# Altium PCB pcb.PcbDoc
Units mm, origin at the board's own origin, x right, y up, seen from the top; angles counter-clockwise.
Board outline 66.48 x 77.37 mm, 2 copper layers (Top Layer, Bottom Layer); 43 components, 40 nets, 214 pads, 135 vias.
Unrouted connection lines stored in the file: 93.
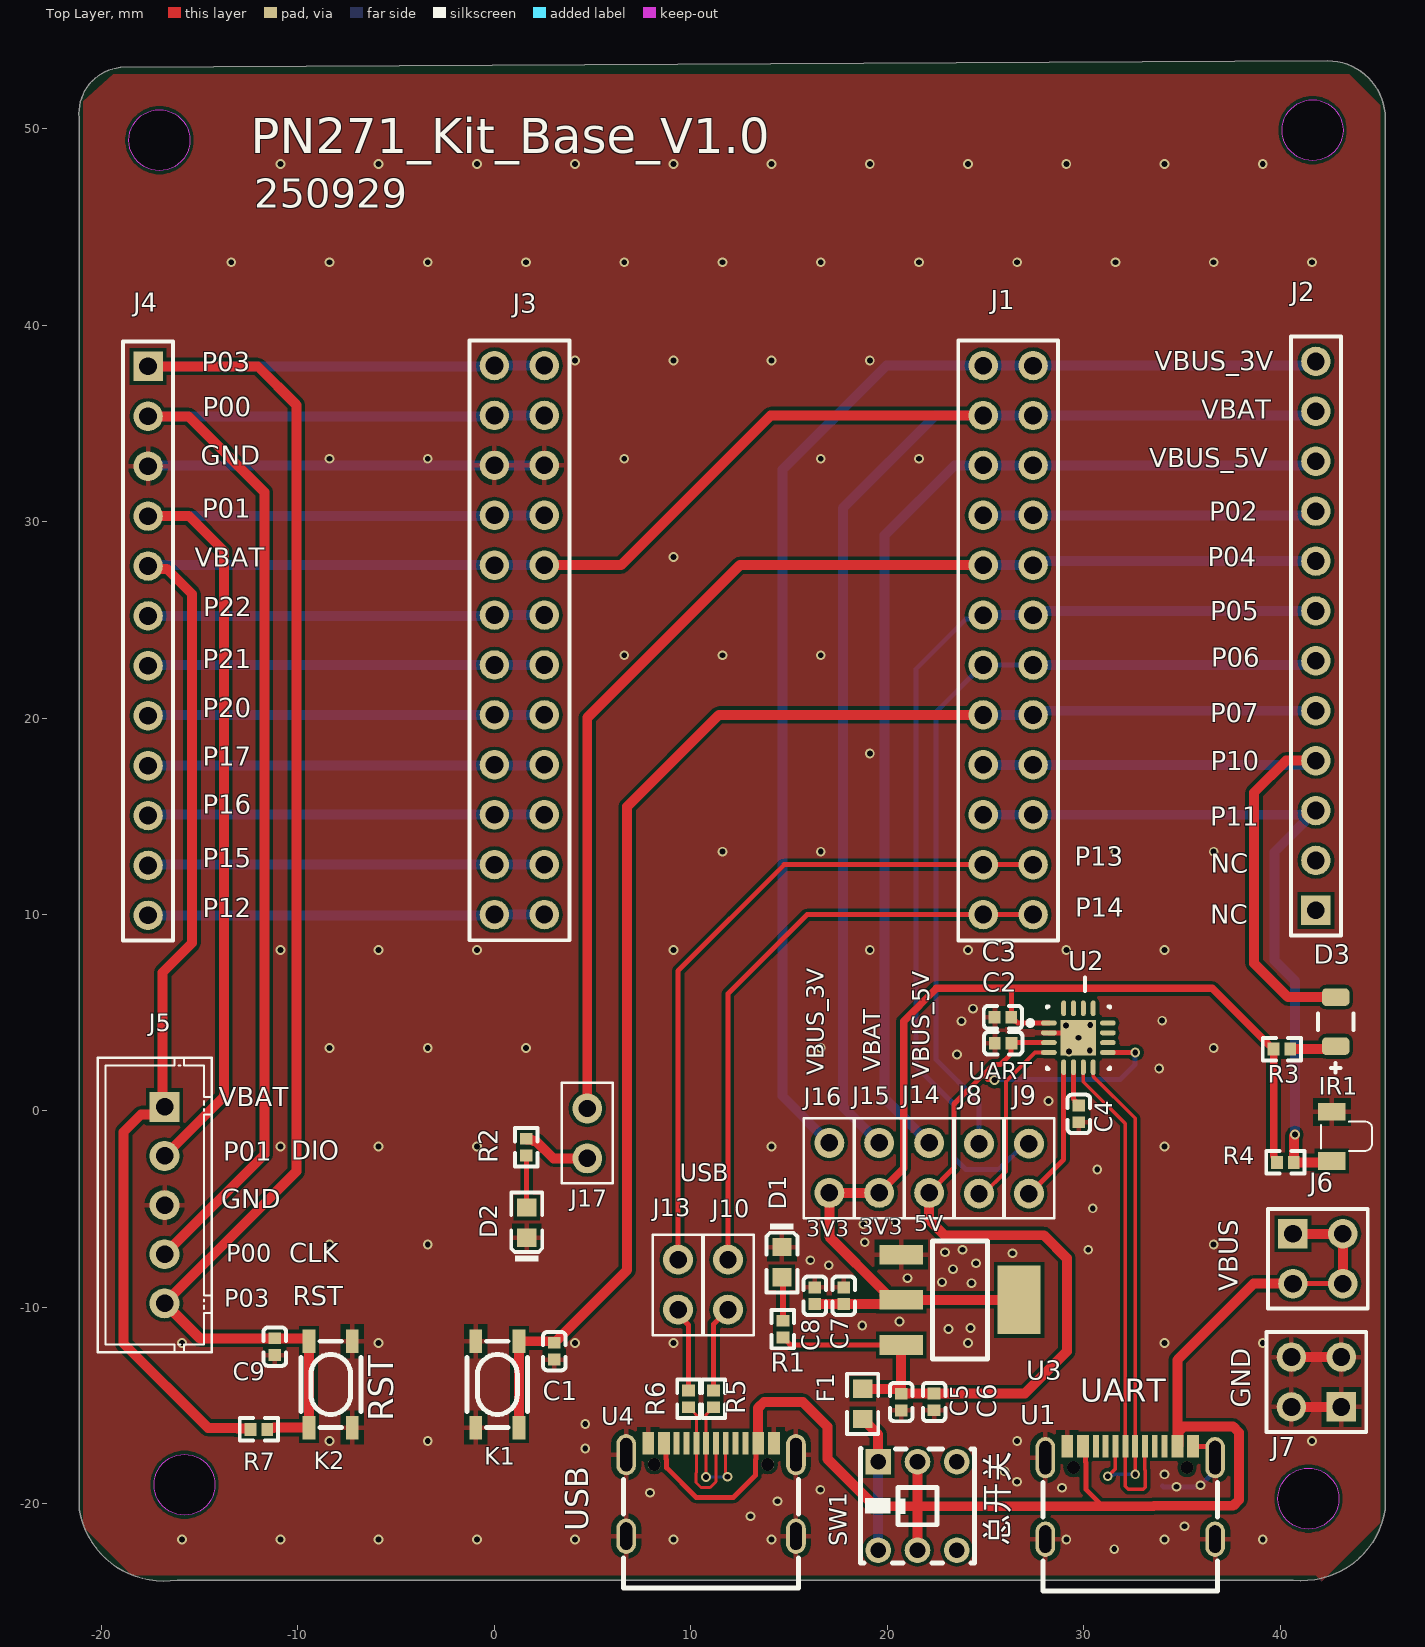
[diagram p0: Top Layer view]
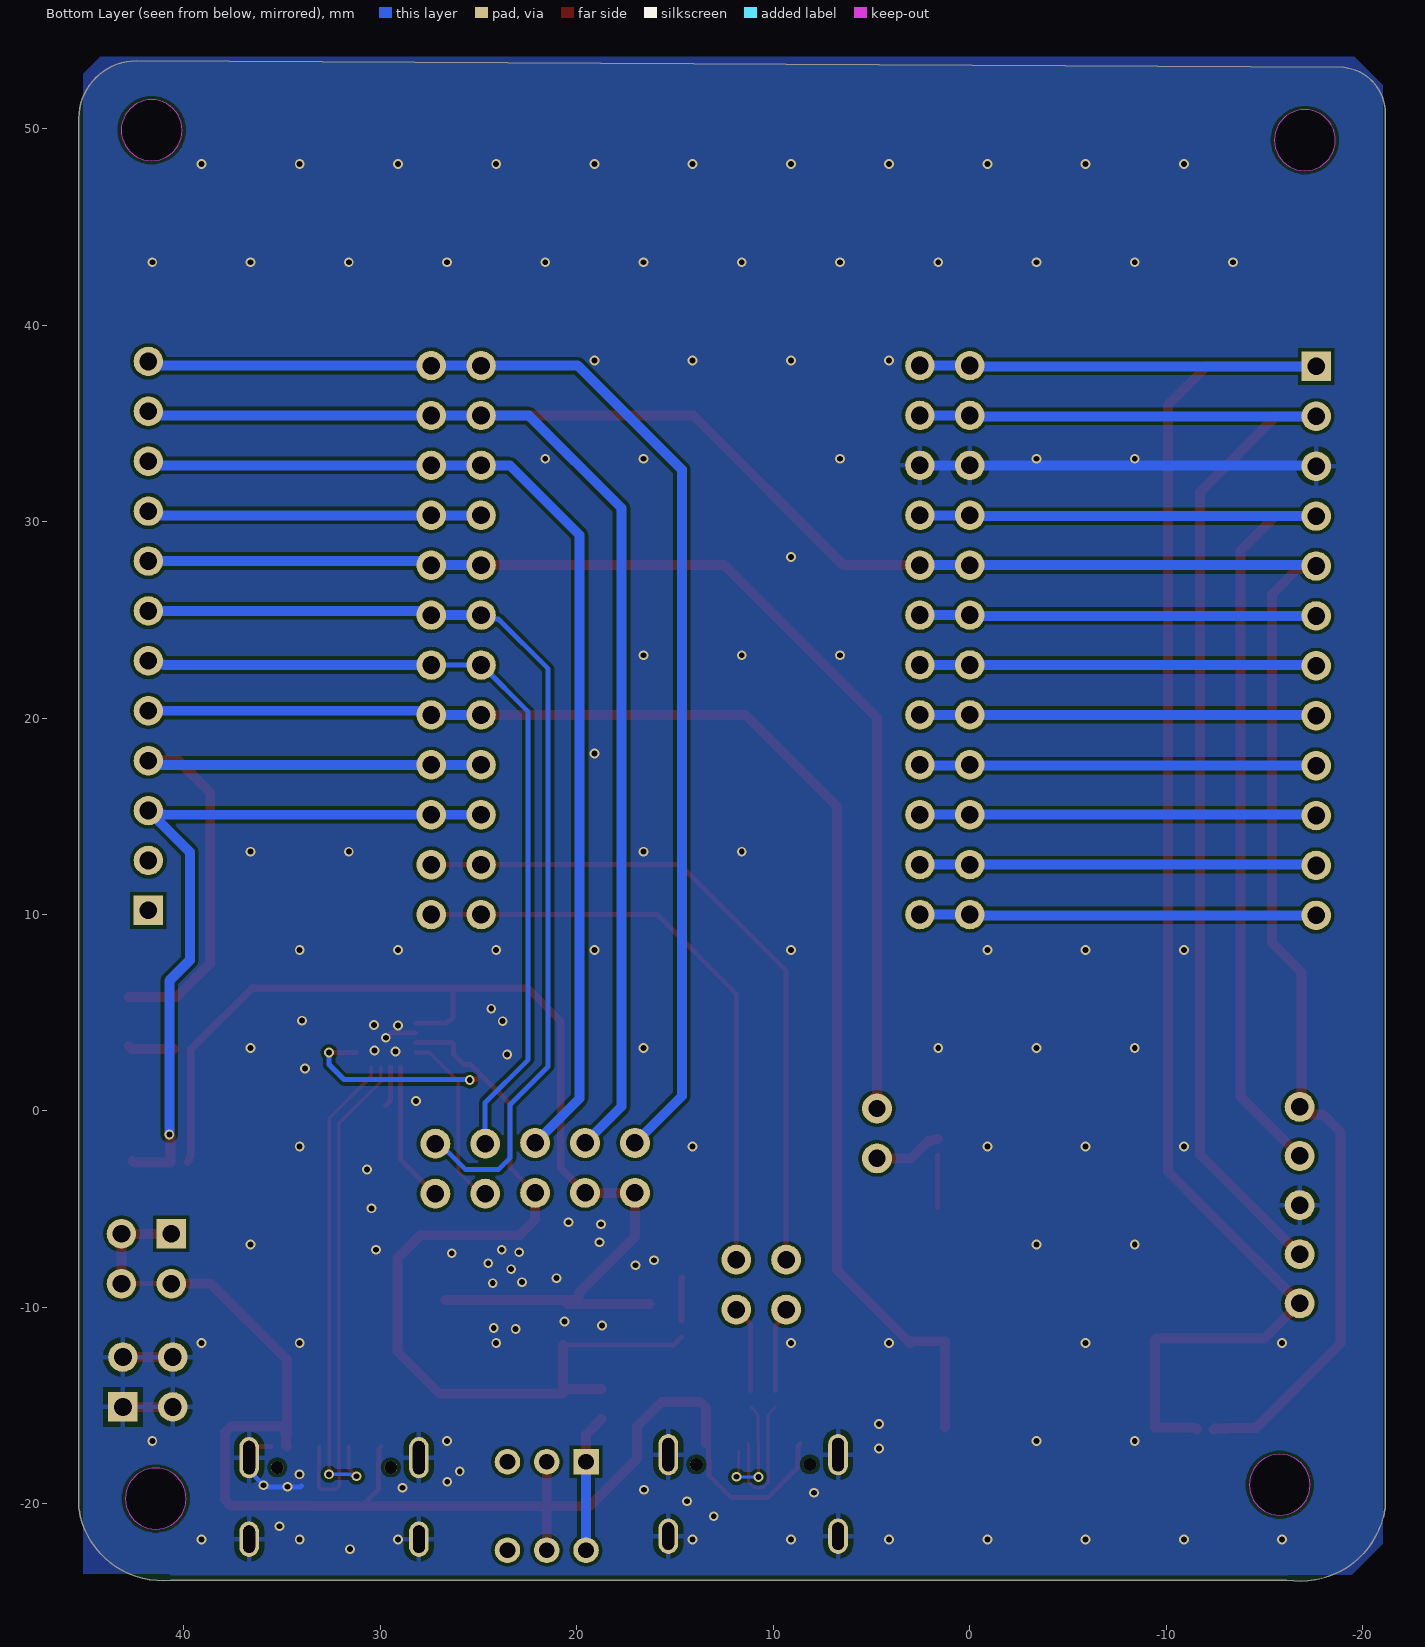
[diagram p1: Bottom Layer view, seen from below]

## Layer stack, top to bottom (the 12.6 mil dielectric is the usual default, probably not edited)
Top Solder: solder mask 0.0102, Solder Resist, Dk 3.5
Top Layer: signal copper 0.0356
Dielectric 1: dielectric 0.32, FR-4, Dk 4.8
Bottom Layer: signal copper 0.0356
Bottom Solder: solder mask 0.0102, Solder Resist, Dk 3.5

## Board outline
-21.13,-20.285 cw(c-20.879,-20.244) -21.133,-20.243 -21.133,-19.254 -21.133,50.559 cw(c-18.809,50.787) -19.051,53.11 cw(c-19.025,52.857) -19.026,53.112 42.417,53.442 cw(c42.418,53.188) 42.418,53.442 cw(c42.418,50.521) 45.339,50.521 cw(c45.085,50.521) 45.339,50.519 45.339,-19.122 45.339,-20.244 cw(c45.085,-20.244) 45.336,-20.283 cw(c41.11,-19.621) 40.667,-23.876 -16.134,-23.876 cw(c-16.827,-19.571)
cut-out: -15.774,-20.575 cw(c-15.774,-19.025) -17.324,-19.025 cw(c-15.774,-19.025) -15.774,-17.475 cw(c-15.774,-19.025) -14.224,-19.025 cw(c-15.774,-19.025)
cut-out: -17.053,47.862 cw(c-17.053,49.412) -18.603,49.412 cw(c-17.053,49.412) -17.053,50.962 cw(c-17.053,49.412) -15.503,49.412 cw(c-17.053,49.412)
cut-out: 41.64,48.37 cw(c41.64,49.92) 40.09,49.92 cw(c41.64,49.92) 41.64,51.47 cw(c41.64,49.92) 43.19,49.92 cw(c41.64,49.92)
cut-out: 41.43,-21.279 cw(c41.43,-19.729) 39.88,-19.729 cw(c41.43,-19.729) 41.43,-18.179 cw(c41.43,-19.729) 42.98,-19.729 cw(c41.43,-19.729)

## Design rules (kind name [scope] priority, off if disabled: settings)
Clearance [All] p1: gap=0.173 ignorepadtopadclearanceinfootprint=FALSE
HoleSize [All] p1: absolutevalues=TRUE maxlimit=3.81 minlimit=0.025 maxpercent=80.000 minpercent=20.000
MinimumSolderMaskSliver [All] p1: minsoldermaskwidth=0.025
PolygonConnect [All] p1: thpad.connectstyle=Relief thpad.reliefconductorwidth=0.254 thpad.reliefentries=4 thpad.polygonreliefangle="90 Angle" thpad.airgapwidth=0.254 smdpad.connectstyle=Relief smdpad.reliefconductorwidth=0.254 smdpad.reliefentries=4 smdpad.polygonreliefangle="90 Angle" smdpad.airgapwidth=0.254 via.connectstyle=Direct via.reliefconductorwidth=0.254 via.reliefentries=4 via.polygonreliefangle="90 Angle" via.airgapwidth=0.254
RoutingVias [All] p1: holewidth=0.3 width=0.5 viastyle="Through Hole" minholewidth=0.3 minwidth=0.5 maxholewidth=0.3 maxwidth=0.5
SilkToSilkClearance [All] p1 off: silktosilkclearance=0.254
SilkToSolderMaskClearance [IsPad] p1 off: minsilkscreentomaskgap=0.254 clearancetoexposedcopper=TRUE
SolderMaskExpansion SolderMaskExpansion_1 [IsVia] p1: expansion=0.102 istentingtop=TRUE
SolderMaskExpansion [All] p2: expansion=0.102 istentingtop=FALSE
UnRoutedNet [All] p1: checkbadconnections=TRUE
Width [All] p1: maxlimit=1.27 minlimit=0.152 preferedwidth=0.203 minimp=50.000000 maximp=50.000000 favimp=50.000000
25 further rules are at their usual default settings.

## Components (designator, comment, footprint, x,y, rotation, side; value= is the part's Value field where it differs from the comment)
C1 "100nF / NC" 0402_C 3.048,-12.224 r90 top
C2 "100nF" 0402_C 25.894,3.449 r180 top
C3 "4.7uF" 0402_C 25.88,4.77 r180 top
C4 "100nF" 0402_C 29.743,-0.146 r270 top
C5 "100nF" 0402_C 20.701,-14.815 r90 top
C6 "10uF" 0402_C 22.377,-14.808 r90 top
C7 "100nF" 0402_C 17.78,-9.405 r270 top
C8 "10uF" 0402_C 16.307,-9.405 r270 top
C9 "100nF / NC" 0402_C -11.176,-11.996 r90 top
D1 "红灯 0603" 0603_LED_S1 14.63,-7.696 r270 top
D2 "绿灯 0603" 0603_LED_S1 1.645,-5.686 r90 top
D3 "IR26-51C/L110/TR8" FP-IR26-51C-L110-TR8-MFG 42.816,4.547 r90 top
F1 "" 0603_R 18.745,-14.91 r90 top
IR1 "PT26-51B/TR8" OPTO-SMD_PT26-51B-TR8 42.621,-1.295 r270 top
J1 "Header 2x12" "Header 2X12" 24.875,37.938 r270 top locked
J2 "nc" HDR1X12 41.808,10.211 r90 top
J3 "Header 2x12" "Header 2X12" 0,37.94 r270 top locked
J4 "nc" HDR1X12 -17.628,37.897 r270 top
J5 "SWD" "XH 1x5" -16.789,0.21 r270 top
J6 "Header 2X2" HDR2X2 40.64,-6.248 r270 top
J7 "Header 2X2" HDR2X2 43.104,-15.062 r90 top
J8 "Header 2" "Header 1x2" 24.663,-1.666 r0 top
J9 "Header 2" "Header 1x2" 27.203,-1.666 r0 top
J10 "Header 2" "Header 1x2" 11.887,-10.109 r180 top
J13 "Header 2" "Header 1x2" 9.347,-10.109 r180 top
J14 "Header 2" "Header 1x2" 22.123,-4.166 r180 top
J15 "Header 2" "Header 1x2" 19.583,-4.166 r180 top
J16 "Header 2" "Header 1x2" 17.043,-4.166 r180 top
J17 "Header 2" "Header 1x2" 4.724,0.127 r0 top
K1 "K2-1808GN-A4SW-04" KEY-SMD_4P-L4.2-W3.2-P2.20-LS5.1-TL 0.152,-13.919 r270 top
K2 "K2-1808GN-A4SW-04" KEY-SMD_4P-L4.2-W3.2-P2.20-LS5.1-TL -8.331,-13.919 r90 top
R1 "1KΩ" 0402_R 14.681,-11.1 r90 top
R2 "1KΩ" 0402_R 1.619,-1.843 r270 top
R3 "100Ω" 0402_R 40.081,3.15 r180 top
R4 "300Ω" 0402_R 40.259,-2.616 r180 top
R5 "0Ω" 0402_R 11.151,-14.649 r270 top
R6 "0Ω" 0402_R 9.881,-14.649 r270 top
R7 "NC" 0402_R -11.989,-16.205 r180 top
SW1 "K8-5851E-L1" SW-TH_6P-L5.8-W5.8-P2.00-LS4.5-TL_K8-5851E-L1 21.533,-20.106 r0 top
U1 "USB_Type-C(Seat-16P)" USB-C-SMD_TYPE-C16PIN 32.36,-19.431 r0 top
U2 "CH343P" QFN16 29.723,3.728 r0 top
U3 "AMS1117-3.3" SOT-223 23.701,-9.613 r180 top
U4 "USB_Type-C(Seat-16P)" USB-C-SMD_TYPE-C16PIN 11.026,-19.279 r0 top

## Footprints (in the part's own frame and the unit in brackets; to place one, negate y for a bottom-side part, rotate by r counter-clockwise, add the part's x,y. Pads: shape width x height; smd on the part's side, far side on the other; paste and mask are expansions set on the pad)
0402_C [mm]
  rect 0.6x0.65 smd mask+0.051: 1(-0.425,0) 2(0.425,0)
  silkscreen extent -0.97,-0.58 0.97,0.58, body extent -0.48,-0.3 0.52,0.3, height 0.2
0402_R [mm]
  rect 0.6x0.65 smd mask+0.051: 1(-0.425,0) 2(0.425,0)
  silkscreen extent -0.97,-0.58 0.97,0.58, body extent -0.57,-0.27 0.58,0.28, height 0.41
0603_LED_S1 [mm]
  rect 0.93x0.98 smd: A(0.77,0) K(-0.77,0)
  silkscreen extent -1.97,-0.79 1.54,0.79, body extent -0.8,-0.4 0.8,0.4, height 0.6
0603_R [mm]
  rect 0.93x0.98 smd: 1(-0.77,0) 2(0.77,0)
  silkscreen extent -1.53,-0.79 1.54,0.79, body extent -0.85,-0.4 0.85,0.4, height 0.56
FP-IR26-51C-L110-TR8-MFG [mm]
  rrect50% 0.9x1.4 smd paste+0 mask+0: 1(-1.25,0) 2(1.25,0)
  silkscreen extent -2.6,-0.9 0.43,0.9, body extent -1.8,-1 1.8,1, height 0.25
HDR1X12 [mm] "Connector; Header; 12 Position"
  rect 1.5x1.5 hole 0.9: 1(0,0)
  round 1.5 hole 0.9: 2(2.54,0) 3(5.08,0) 4(7.62,0) 5(10.16,0) 6(12.7,0) 7(15.24,0) 8(17.78,0) 9(20.32,0) 10(22.86,0) 11(25.4,0) 12(27.94,0)
  silkscreen extent -1.27,-1.27 29.21,1.27
HDR2X2 [mm] "Connector; Header; 2x2 Position"
  rect 1.5x1.5 hole 0.9: 1(0,0)
  round 1.5 hole 0.9: 2(0,2.54) 3(2.54,0) 4(2.54,2.54)
  silkscreen extent -1.27,-1.27 3.81,3.81
"Header 1x2" [mil] "Header 1x2,2.54mm"
  round 60 hole 35: 1(0,0) 2(0,-100)
  silkscreen extent -51,-150 51,51, body extent -50,-150 50,50, height 335
"Header 2X12" [mm] "Connector; Header; 12x2 Position"
  round 1.5 hole 0.9: 1(0,0) 2(0,2.54) 3(2.54,0) 4(2.54,2.54) 5(5.08,0) 6(5.08,2.54) 7(7.62,0) 8(7.62,2.54) 9(10.16,0) 10(10.16,2.54) 11(12.7,0) 12(12.7,2.54) 13(15.24,0) 14(15.24,2.54) 15(17.78,0) 16(17.78,2.54) 17(20.32,0) 18(20.32,2.54) 19(22.86,0) 20(22.86,2.54) 21(25.4,0) 22(25.4,2.54) 23(27.94,0) 24(27.94,2.54)
  silkscreen extent -1.27,-1.27 29.25,3.81, body extent -1.27,-1.27 29.21,3.81, height 8.5
KEY-SMD_4P-L4.2-W3.2-P2.20-LS5.1-TL [mm]
  rect 1.2x0.65 smd: 1(-2.2,1.1) 2(2.2,1.1) 3(-2.2,-1.1) 4(2.2,-1.1)
  silkscreen extent -2.2,-1.55 2.2,1.52
OPTO-SMD_PT26-51B-TR8 [mm]
  rect 0.9x1.4 smd paste+0 mask+0.05: 1(-1.25,0) 2(1.25,0)
  silkscreen extent -0.76,-0.55 0.74,2.05
QFN16 [mm]
  oval 0.8x0.25 smd: 1(-1.5,0.75) 2(-1.5,0.25) 3(-1.5,-0.25) 4(-1.5,-0.75) 9(1.5,-0.75) 10(1.5,-0.25) 11(1.5,0.25) 12(1.5,0.75)
  oval 0.25x0.8 smd: 5(-0.75,-1.5) 6(-0.25,-1.5) 7(0.25,-1.5) 8(0.75,-1.5) 13(0.75,1.5) 14(0.25,1.5) 15(-0.25,1.5) 16(-0.75,1.5)
  rect 1.8x1.8 smd: 17(0,0)
  silkscreen extent -2.57,-1.6 1.6,1.6, body extent -1.58,-1.58 1.58,1.58, height 1
SOT-223 [mm]
  rect 2.2x1 smd: 1(3,-2.3) 2(3,0) 3(3,2.3)
  rect 2.2x3.5 smd: 2(-3,0)
  silkscreen extent -1.4,-3 1.4,3, body extent -3.49,-3.24 3.49,3.24, height 1.64
SW-TH_6P-L5.8-W5.8-P2.00-LS4.5-TL_K8-5851E-L1 [mm]
  rect 1.3x1.3 hole 0.8 paste+0 mask+0.05: 1(-2,2.25)
  round 1.3 hole 0.8 paste+0 mask+0.05: 2(0,2.25) 3(2,2.25) 4(-2,-2.25) 5(0,-2.25) 6(2,-2.25)
  silkscreen extent -2.9,-2.9 2.9,2.92
USB-C-SMD_TYPE-C16PIN [mm]
  oval 1x2.1 hole 0.6 slot 1.7 at 90 deg: 1(-4.32,1.787) 2(4.32,1.787)
  oval 1x1.8 hole 0.6 slot 1.4 at 90 deg: 3(-4.32,-2.362) 4(4.32,-2.362)
  rect 0.6x1.15 smd: A1/B12(-3.2,2.362) A4/B9(-2.4,2.362) A9/B4(2.4,2.362) A12/B1(3.2,2.362)
  rect 0.3x1.15 smd: A5(-1.25,2.362) A6(-0.25,2.362) A7(0.25,2.362) A8(-1.75,2.362) B5(1.75,2.362) B6(0.75,2.362) B7(-0.75,2.362) B8(1.25,2.362)
  round 0.65 hole 0.65 unplated: ""(-2.89,1.288) ""(2.89,1.288)
  silkscreen extent -4.45,-5 4.45,0.52, body extent -4.47,-5 4.47,2.9, height 3.2
"XH 1x5" [mil] "XH 1x5,2.5mm"
  rect 60x60 / inner round 60 / far side round 60 hole 35: 1(0,0)
  round 60 hole 35: 2(98.43,0) 3(196.85,0) 4(295.28,0) 5(393.7,0)
  silkscreen extent -98,-134 492,94

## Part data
C1 C2 C4 C5 C7 C9: library part "0402 100nF (104) 10% 16V", "贴片电容", Package=0402, SuppliersPartNumber=C1525
C3: library part "0402 4.7uF (475) 20% 10V", "贴片电容", Package=0402, SuppliersPartNumber=C23733
C6 C8: library part "0402 10uF (106) 20% 6.3V", "贴片电容", Package=0402, SuppliersPartNumber=C15525
D1: library part "0603 红灯", "发光二极管", Package=0603, SuppliersPartNumber=C2286
D2: library part "0603 绿灯", "发光二极管", Package=0603, SuppliersPartNumber=C72043
D3: "EMITTER IR 940NM 65MA SMD", Case/Package=SMD/SMT, Forward Current=65mA, Forward Voltage=1.2V, Max Operating Temperature=85°C, Min Operating Temperature=-25°C, Package Quantity=1, Power Rating=130mW
F1: library part Res1, "Resistor"
IR1: Collector - Emitter Voltage VCEO=30V, Current - Collector(Ic)=20mA, Current - Dark(Id)=100nA, Dissipation Power(Max)=75mW, JLCPCB Part Class="Extended Part", LCSC Part Name=940nm的NPN光电三极管, Manufacturer=EVERLIGHT(亿光), Operating Temperature=-25℃~+85℃
J1 J3: "Header 2x11,2.54mm"
J2 J4: library part "Header 12", "Header, 12-Pin"
J5: library part "Header 1x5", "Header 1x5,2.54mm"
J6 J7: "Header, 2-Pin, Dual row"
J8 J9 J10 J13 J14 J15 J16 J17: library part SW-SPST, "Header, 2-Pin"
K1 K2: Contact Current=50mA, Insulation Resistance=100MΩ, JLCPCB Part Class="Extended Part", Manufacturer=韩国韩荣, Operating Force=250gf, Operating Temperature=-25℃~+85℃, Voltage Rating (DC)=12V
R1 R2 R7: library part "0402 1KΩ (1001) 1%", "贴片电阻", Package=0402, SuppliersPartNumber=C11702
R3 R4: library part "0402 300Ω (3000) 1%", "贴片电阻", Package=0402, SuppliersPartNumber=C25102
R5 R6: library part "0402 0Ω (0R0) 1%", "贴片电阻", Package=0402, SuppliersPartNumber=C17168
SW1: Actuator/Cap Color=白色, Contact Current=100mA, IP Rating=-, JLCPCB Part Class="Extended Part", Manufacturer=韩国韩荣, Operating Force=1.8N, Operating Temperature=-25℃~+80℃, Voltage Rating=30V
U2: "USB 转高速串口芯片"
U3: library part "SOT-223 AMS1117-3.3", "低压差线性稳压(LDO)", Package=SOT-223, SuppliersPartNumber=C6186

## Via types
v1: diameter 0.5, hole 0.3, Top Layer to Bottom Layer, tented both sides, 135 vias

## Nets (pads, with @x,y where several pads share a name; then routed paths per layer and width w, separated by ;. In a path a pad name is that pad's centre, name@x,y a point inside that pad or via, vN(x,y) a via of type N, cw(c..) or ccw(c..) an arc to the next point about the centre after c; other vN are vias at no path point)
3V3_1: C3.1 C7.2 C8.2 J15.1 J16.1 R3.2 R4.2 U2.1 U3.2 | length 59.6
  Top Layer w0.254: 26.305,6.181 C3.1 26.305,4.745 26.478,4.572 26.534,4.572 26.627,4.478 U2.1
  Top Layer w0.381: J15.1 20.828,-2.921 20.828,4.572 22.499,6.243 26.244,6.243 ; 26.305,6.181 26.244,6.243 ; R3.2@39.49,3.284 36.531,6.243 26.244,6.243 ; R3.2 39.656,-2.305 39.724,-2.373 39.724,-2.507 R4.2
  Top Layer w0.508: C8.2 C7.2 20.101,-9.83 20.484,-9.83 U3.2@20.701,-9.613 ; J15.1 J16.1 17.043,-6.401 19.855,-9.212 19.855,-9.367 20.101,-9.613 20.484,-9.613 U3.2@20.701,-9.613 ; U3.2@26.701,-9.613 U3.2@20.701,-9.613
5V_1: C2.1 C5.2 C6.2 F1.2 J14.1 R1.1 U2.3 U2.9 U3.3 | length 55.3
  Top Layer w0.254: R1.1 14.706,-11.525 14.879,-11.698 14.879,-11.723 15.069,-11.913 U3.3 ; J14.1 23.393,-2.896 23.393,0.356 24.879,1.841 ; v1(25.451,1.575) 25.411,1.615 25.106,1.615 24.879,1.841 ; U2.3 26.348,3.478 C2.1 26.285,3.415 26.285,2.892 25.756,2.362 25.4,2.362 24.879,1.841 ; U2.9 32.607,2.978 v1(32.614,2.972)
  Top Layer w0.508: F1.2 C5.2@20.451,-14.14 ; U3.3 C5.2 20.708,-14.383 C6.2 26.993,-14.383 29.134,-12.243 29.134,-7.493 27.965,-6.325 22.911,-6.325 22.708,-6.122 22.123,-5.537 J14.1
  Bottom Layer w0.254: v1(25.451,1.575) 25.476,1.6 31.852,1.6 32.614,2.362 v1(32.614,2.972)
DM_1: R6.2 U4.A7 U4.B7 | length 7.2
  Top Layer w0.152: R6.2 9.906,-15.074 10.129,-15.298 10.129,-15.323 10.276,-15.469 U4.B7 10.276,-18.41 10.261,-18.424 10.261,-18.912 10.26,-18.913 10.508,-19.16 10.979,-19.16 11.276,-18.864 U4.A7
DP_1: R5.2 U4.A6 U4.B6 | length 6.2
  Top Layer w0.152: v1(10.76,-18.631) U4.A6@10.76,-16.916 ; U4.A6 10.776,-15.449 10.902,-15.323 10.902,-15.298 11.126,-15.074 R5.2 ; U4.B6@11.76,-17.323 11.76,-18.416 11.868,-18.524 v1(11.868,-18.618)
  Bottom Layer w0.152: v1(10.76,-18.631) 11.855,-18.631 v1(11.868,-18.618)
GND: C1.1 C2.2 C3.2 C4.2 C5.1 C6.1 C7.1 C8.1 C9.1 D1.K D2.K IR1.1 J3.5 J3.6 J4.3 J5.3 J7.1 J7.2 J7.3 J7.4 K1.3 K1.4 K2.3 K2.4 U1.1 U1.2 U1.3 U1.4 U1.A1/B12 U1.A12/B1 U2.2 U2.17 U3.1 U4.1 U4.2 U4.3 U4.4 U4.A1/B12 U4.A12/B1 | length 32.1
  Top Layer w0.254: U2.2 29.473,3.978 v1(29.723,3.728) ; U1.A12/B1 36.335,-17.069 36.68,-17.413 U1.2
  Top Layer w0.508: J7.2 J7.1 ; J7.4 J7.3
  Bottom Layer w0.254: 34.011,-19.075 34.061,-19.126 v1(34.722,-19.126) 35.691,-19.126 35.72,-19.097 35.894,-19.097 v1(35.941,-19.05) 36.68,-18.311 U1.2
  Bottom Layer w0.508: J4.3 -17.584,32.86 J3.5 J3.6
  other v1: 31.547,-22.301 -15.893,-21.802 -10.893,-21.802 -5.893,-21.802 -0.893,-21.802 4.107,-21.802 9.107,-21.802 14.107,-21.802 29.107,-21.802 34.107,-21.802 39.107,-21.802 35.128,-21.133 13.03,-20.625 14.402,-19.863 7.925,-19.431 16.586,-19.279 28.88,-19.177 26.594,-18.872 34.112,-18.491 25.959,-18.339 4.623,-17.17 -8.393,-16.802 -3.393,-16.802 26.607,-16.802 41.607,-16.802 4.623,-15.926 -15.893,-11.802 -5.893,-11.802 4.107,-11.802 9.107,-11.802 24.107,-11.802 34.107,-11.802 39.107,-11.802 23.114,-11.1 24.232,-11.049 18.72,-10.922 20.625,-10.719 24.282,-8.763 22.784,-8.712 21.031,-8.509 23.343,-8.052 17.018,-7.849 24.511,-7.747 16.078,-7.595 26.365,-7.239 22.936,-7.188 23.825,-7.061 30.226,-7.061 -8.393,-6.802 -3.393,-6.802 36.607,-6.802 18.847,-6.68 18.771,-5.766 20.422,-5.664 30.455,-4.953 30.683,-2.972 -10.893,-1.802 -5.893,-1.802 -0.893,-1.802 14.107,-1.802 34.107,-1.802 28.194,0.508 33.833,2.159 23.546,2.87 29.235,3.023 30.302,3.073 -8.393,3.198 -3.393,3.198 1.607,3.198 16.607,3.198 36.607,3.198 29.098,4.353 30.328,4.369 23.774,4.572 33.985,4.597 24.359,5.207 -10.893,8.198 -5.893,8.198 -0.893,8.198 9.107,8.198 19.107,8.198 24.107,8.198 29.107,8.198 34.107,8.198 11.607,13.198 16.607,13.198 31.607,13.198 36.607,13.198 19.107,18.198 6.607,23.198 11.607,23.198 16.607,23.198 9.107,28.198 -8.393,33.198 -3.393,33.198 6.607,33.198 16.607,33.198 21.607,33.198 4.107,38.198 9.107,38.198 14.107,38.198 19.107,38.198 -13.393,43.198 -8.393,43.198 -3.393,43.198 1.607,43.198 6.607,43.198 11.607,43.198 16.607,43.198 21.607,43.198 26.607,43.198 31.607,43.198 36.607,43.198 41.607,43.198 -10.893,48.198 -5.893,48.198 -0.893,48.198 4.107,48.198 9.107,48.198 14.107,48.198 19.107,48.198 24.107,48.198 29.107,48.198 34.107,48.198 39.107,48.198
NetC4_1: C4.1 U2.6 | length 2.1
  Top Layer w0.254: U2.6 29.473,0.601 29.545,0.528 29.545,0.452 29.718,0.279 C4.1
NetD1_A: D1.A R1.2 | length 2.2
  Top Layer w0.305: D1.A 14.681,-8.517 R1.2
NetD2_A: D2.A R2.2 | length 2.7
  Top Layer w0.254: R2.2 1.645,-2.293 D2.A
NetD3_1: D3.1 R3.1 | length 2.4
  Top Layer w0.508: R3.1 42.669,3.15 D3.1
NetF1_1: F1.1 SW1.1 SW1.4 | length 7
  Top Layer w0.508: F1.1 18.77,-15.68 18.981,-15.891 18.981,-15.916 19.533,-16.467 SW1.1
  Bottom Layer w0.508: SW1.4 SW1.1
NetJ8_2: J8.2 U2.4 | length 9.2
  Top Layer w0.191: J8.2@24.663,-4.242 24.867,-4.242 26.035,-3.073 26.035,1.499 27.515,2.978 U2.4
NetJ9_2: J9.2 U2.5 | length 7.2
  Top Layer w0.254: J9.2@27.203,-4.242 28.973,-2.473 U2.5
NetJ10_1: J10.1 R5.1 | length 4.4
  Top Layer w0.254: R5.1 11.151,-10.846 J10.1
NetJ13_1: J13.1 R6.1 | length 4.3
  Top Layer w0.254: J13.1 9.347,-10.36 9.881,-10.893 R6.1
NetJ17_2: J17.2 R2.1 | length 3.5
  Top Layer w0.508: R2.1 1.665,-1.464 1.916,-1.464 1.988,-1.536 2.123,-1.536 3,-2.413 J17.2
NetU1_A6: U1.A6 U1.B6 U2.7 | length 25.5
  Top Layer w0.178: U2.7 29.973,1.498 32.11,-0.639 U1.A6 32.11,-18.265 32.097,-18.277 32.097,-19.092 32.266,-19.262 33.026,-19.262 33.13,-19.157 33.13,-18.277 33.11,-18.256 U1.B6
NetU1_A7: U1.A7 U1.B7 U2.8 | length 24.7
  Top Layer w0.178: U2.8 30.475,2.226 30.475,1.758 32.61,-0.377 U1.A7 32.61,-18.487 v1(32.614,-18.491) ; v1(31.217,-18.593) 31.61,-18.2 U1.B7
  Bottom Layer w0.178: v1(31.217,-18.593) 31.278,-18.531 31.486,-18.531 31.526,-18.491 v1(32.614,-18.491)
P00_1: J3.3 J3.4 J4.2 J5.4 | length 68.6
  Top Layer w0.508: J4.2 -15.57,35.357 -11.709,31.496 -11.709,-2.21 J5.4
  Bottom Layer w0.508: J4.2 -0.043,35.357 J3.3 J3.4
P01_1: J3.7 J3.8 J4.4 J5.2 | length 56.8
  Top Layer w0.508: J4.4 -15.545,30.277 -13.767,28.499 -13.767,0.733 J5.2
  Bottom Layer w0.508: J4.4 -0.043,30.277 J3.7 J3.8
P02_1: J1.7 J1.8 J2.9 | length 17.6
  Top Layer w0.508: J2.9@41.327,30.318 41.54,30.531 J2.9
  Bottom Layer w0.508: J1.7 J1.8 41.327,30.318 41.54,30.531 J2.9
P03_1: C9.2 J3.1 J3.2 J4.1 J5.5 K2.1 K2.2 R7.1 | length 91.8
  Top Layer w0.508: J4.1 -12.04,37.897 -10.084,35.941 -10.084,-3.084 -12.242,-5.242 J5.5 -16.779,-9.79 -14.998,-11.571 C9.2 -9.502,-11.571 -9.431,-11.642 K2.2 K2.1 -11.22,-16.119 -11.235,-16.134 -11.518,-16.134 -11.564,-16.18 R7.1
  Bottom Layer w0.508: J4.1 -0.043,37.897 J3.1 J3.2
P04_1: J1.9 J1.10 J2.8 J17.1 | length 60.3
  Top Layer w0.508: J17.1 4.724,20.015 12.487,27.778 J1.9
  Bottom Layer w0.508: J1.9 J1.10 27.684,27.778 27.897,27.991 J2.8
P05_1: J1.11 J1.12 J2.7 J9.1 | length 51.9
  Bottom Layer w0.254: J1.11 24.669,25.032 23.99,25.032 21.463,22.504 21.463,2.261 23.393,0.33 23.393,-2.388 23.978,-2.972 25.679,-2.972 26.986,-1.666 J9.1
  Bottom Layer w0.508: J1.11 J1.12 27.684,25.238 27.897,25.451 J2.7
P06_1: J1.13 J1.14 J2.6 J8.1 | length 43.3
  Bottom Layer w0.254: J8.1 24.663,0.432 22.479,2.616 22.479,20.32 24.857,22.698 J1.13 J1.14
  Bottom Layer w0.508: J1.14 41.015,22.698 41.038,22.721 41.619,22.721 J2.6
P07_1: C1.2 J1.15 J1.16 J2.5 K1.1 K1.2 | length 72.1
  Top Layer w0.508: K1.2 K1.1 2.943,-11.719 3.023,-11.799 C1.2 3.073,-11.799 3.119,-11.753 3.119,-11.728 6.756,-8.091 6.756,15.494 11.42,20.158 J1.15
  Bottom Layer w0.508: J1.15 J1.16 27.684,20.158 27.897,20.371 J2.5
P10_1: D3.2 J1.17 J1.18 J2.4 | length 34.4
  Top Layer w0.508: J2.4 40.284,17.831 38.659,16.205 38.659,7.518 40.381,5.797 D3.2
  Bottom Layer w0.508: J1.17 J1.18 41.327,17.618 41.54,17.831 J2.4
P11_1: IR1.2 J1.19 J1.20 J2.3 R4.1 | length 38.5
  Top Layer w0.508: v1(40.742,-1.194) 40.742,-1.219 40.684,-1.277 R4.1 42.55,-2.616 IR1.2 ; J2.3@41.327,15.078 41.54,15.291 J2.3
  Bottom Layer w0.508: J1.19 J1.20 41.015,15.078 41.038,15.101 J2.3@41.619,15.101 ; v1(40.742,-1.194) 40.742,6.629 39.7,7.671 39.7,13.183 J2.3@41.619,15.101 ; J2.3 J2.3@41.619,15.101
P12_1: J3.23 J3.24 J4.12 | length 20.2
  Bottom Layer w0.508: J4.12 -0.043,9.957 J3.23 J3.24
P13_1: J1.21 J1.22 J13.2 | length 35
  Top Layer w0.254: J13.2 9.347,7.137 14.748,12.538 J1.21 J1.22
P14_1: J1.23 J1.24 J10.2 | length 30.7
  Top Layer w0.254: J10.2 11.887,5.969 15.916,9.998 J1.23 J1.24
P15_1: J3.21 J3.22 J4.11 | length 20.2
  Bottom Layer w0.508: J4.11 -17.584,12.54 J3.21 J3.22
P16_DIP_1: J3.19 J3.20 J4.10 | length 20.2
  Bottom Layer w0.508: J4.10 -17.584,15.08 J3.19 J3.20
P17_DIP_1: J3.17 J3.18 J4.9 | length 20.2
  Bottom Layer w0.508: J4.9 2.497,17.577 J3.18
P20_1: J3.15 J3.16 J4.8 | length 20.2
  Bottom Layer w0.508: J4.8 -17.584,20.16 J3.15 J3.16
P21_1: J3.13 J3.14 J4.7 | length 20.2
  Bottom Layer w0.508: J4.7 -17.584,22.7 J3.13 J3.14
P22_1: J3.11 J3.12 J4.6 | length 20.2
  Bottom Layer w0.508: J4.6 -0.043,25.197 J3.11 J3.12
VBAT_1: J1.3 J1.4 J2.11 J3.9 J3.10 J4.5 J5.1 J15.2 R7.2 | length 156.1
  Top Layer w0.508: J4.5 -17.473,27.582 -16.66,27.582 -15.392,26.314 -15.392,8.547 -16.891,7.049 -16.891,0.312 J5.1 -17.179,-0.18 -17.985,-0.18 -18.872,-1.067 -18.872,-11.836 -14.583,-16.125 -13.113,-16.125 -13.067,-16.172 -12.447,-16.172 R7.2 ; J3.10 6.444,27.78 14.062,35.398 J1.3
  Bottom Layer w0.508: J4.5 -17.584,27.78 J3.9 J3.10 ; J15.2 17.729,0.229 17.729,30.683 22.444,35.398 J1.3 J1.4 41.327,35.398 41.54,35.611 J2.11
VBUS: J6.1 J6.2 J6.3 J6.4 SW1.2 SW1.5 U1.A4/B9 U1.A9/B4 U4.A4/B9 U4.A9/B4 | length 72.6
  Top Layer w0.254: U4.A4/B9 8.742,-17.032 8.742,-17.706 8.766,-17.73 8.766,-18.164 10.262,-19.66 12.167,-19.66 13.286,-18.54 13.286,-17.73 13.31,-17.706 13.31,-17.032 U4.A9/B4 ; U1.A4/B9 30.076,-17.185 30.076,-17.858 30.099,-17.882 30.099,-19.254 30.963,-20.117 ; J6.3@40.869,-8.788 J6.4
  Top Layer w0.508: U4.A9/B4 13.426,-15.106 13.723,-14.808 15.697,-14.808 16.942,-16.053 16.942,-17.704 19.355,-20.117 21.533,-20.117 ; SW1.5 21.533,-20.117 ; SW1.2 21.533,-20.117 ; U1.A9/B4 34.806,-17.023 34.806,-16.507 34.828,-16.485 34.828,-16.315 35.081,-16.062 37.599,-16.062 37.897,-16.359 37.897,-19.794 37.599,-20.091 33.579,-20.091 33.553,-20.117 30.963,-20.117 21.533,-20.117 ; 34.76,-16.485 34.76,-12.662 38.633,-8.788 J6.3 J6.3@40.869,-8.788 ; J6.1 42.951,-6.248 43.18,-6.477 J6.4
VBUS_3V_1: J1.1 J1.2 J2.12 J16.2 | length 64.7
  Bottom Layer w0.508: J16.2 14.656,0.762 14.656,32.639 19.955,37.938 J1.1 J1.2 41.327,37.938 41.54,38.151 J2.12
VBUS_5V_1: J1.5 J1.6 J2.10 J14.2 | length 55.4
  Bottom Layer w0.508: J14.2 19.863,0.635 19.863,29.312 23.409,32.858 J1.5 J1.6 41.327,32.858 41.54,33.071 J2.10
pads on no net: J2.1 J2.2 SW1.3 SW1.6 U1. U1.A5 U1.A8 U1.B5 U1.B8 U2.10 U2.11 U2.12 U2.13 U2.14 U2.15 U2.16 U4. U4.A5 U4.A8 U4.B5 U4.B8

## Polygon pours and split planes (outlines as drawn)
GND on Bottom Layer "GND_L02_P001" (solid, remove dead copper, pour order 1): -16.154,-23.622 40.68,-23.622 40.756,-23.546 45.11,-23.546 45.11,52.781 44.247,53.645 -19.558,53.645 -21.006,52.197 -21.006,-22.022 -19.431,-23.597 -17.323,-23.597
GND on Top Layer "GND_L01_P000" (solid, remove dead copper, pour order 0): -19.4,52.762 -18.319,52.762 43.504,52.762 45.085,51.181 45.085,-20.955 42.113,-23.927 41.808,-23.622 -18.466,-23.622 -20.93,-21.158 -20.93,51.398

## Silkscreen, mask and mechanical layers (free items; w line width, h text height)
Top Overlay:
  lines w0.203: 30.053,6.116 30.053,6.802
  text "PN271_Kit_Base_V1.0" at -12.395,48.158 h3.05
  text "250929" at -12.234,45.497 h2.54
  text "VBUS_3V" at 33.604,37.376 h1.65
  text "P03" at -14.884,37.307 h1.65
  text "P00" at -14.834,35.04 h1.65
  text "VBAT" at 35.966,34.9 h1.65
  text "GND" at -14.935,32.557 h1.65
  text "VBUS_5V" at 33.325,32.423 h1.65
  text "P01" at -14.859,29.865 h1.65
  text "P02" at 36.373,29.712 h1.65
  text "P04" at 36.297,27.401 h1.65
  text "VBAT" at -15.24,27.381 h1.65
  text "P22" at -14.808,24.841 h1.65
  text "P05" at 36.424,24.658 h1.65
  text "P06" at 36.474,22.27 h1.65
  text "P21" at -14.834,22.2 h1.65
  text "P20" at -14.834,19.705 h1.65
  text "P07" at 36.443,19.451 h1.65
  text "P17" at -14.834,17.253 h1.65
  text "P10" at 36.449,17.012 h1.65
  text "P16" at -14.834,14.809 h1.65
  text "P11" at 36.443,14.199 h1.65
  text "P13" at 29.547,12.149 h1.65
  text "P15" at -14.834,12.085 h1.65
  text "NC" at 36.449,11.804 h1.65
  text "P14" at 29.572,9.564 h1.65
  text "P12" at -14.834,9.524 h1.65
  text "NC" at 36.443,9.188 h1.65
  text "VBAT" at 19.939,2.007 h1.5 r90
  text "VBUS_3V" at 17.058,1.829 h1.5 r90
  text "VBUS_5V" at 22.443,1.676 h1.5 r90
  text "UART" at 24.105,1.313 h1.5
  text "VBAT" at -14.021,-0.102 h1.65
  text "DIO" at -10.338,-2.825 h1.65
  text "P01" at -13.792,-2.876 h1.65
  text "USB" at 9.423,-3.886 h1.52
  text "GND" at -13.894,-5.289 h1.65
  text "5V" at 21.361,-6.401 h1.4
  text "3V3" at 18.596,-6.57 h1.4
  text "3V3" at 15.875,-6.682 h1.4
  text "P00" at -13.64,-7.976 h1.52
  text "CLK" at -10.439,-8.033 h1.65
  text "VBUS" at 38.156,-9.169 h1.65 r90
  text "RST" at -10.262,-10.216 h1.65
  text "P03" at -13.741,-10.262 h1.52
  text "GND" at 38.791,-15.113 h1.65 r90
  text "UART" at 29.82,-15.189 h2
  text "RST" at -4.725,-15.799 h2.16 r90
  text "USB" at 5.158,-21.387 h2 r90
  text "总开关" at 26.543,-22.123 h2 r90
Mechanical 1:
  circle w0.127: c-15.773,-18.974 r1.558
  circle w0.127: c41.478,-19.761 r1.558
  circle w0.127: c41.605,49.86 r1.558
  circle w0.127: c-17.069,49.403 r1.558
  lines w0.508: 40.488,-23.597 ccw(c41.11,-19.621) 45.085,-20.244 45.085,-19.122 45.085,50.521 ccw(c42.418,50.521) 42.418,53.188 -19.025,52.857 ccw(c-18.809,50.787) -20.879,50.571 -20.879,-19.254 -20.879,-20.244 ccw(c-16.827,-19.571) -16.154,-23.622 40.792,-23.622
Mechanical 15:
  lines w1: -5.359,8.128 -5.102,51.127 31.801,51.054 ; -5.222,8.018 31.775,7.595 32.033,50.594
